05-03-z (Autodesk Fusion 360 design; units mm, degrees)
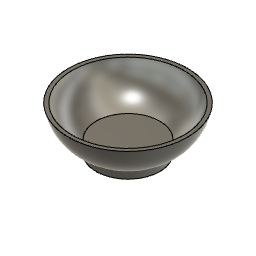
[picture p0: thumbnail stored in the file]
sketch "スケッチ1" plane through (0, 0, 0) normal (0, 0, 1) x axis (1, 0, 0)
  line L1 (-7, -2) -> (-8, -2)
  line L2 (-7, 0) -> (-7, -2)
  line L3 (-8, 0) -> (-7, 0)
  line L4 (-8, -2) -> (-8, 0)
  line L5 (0, 22.5) -> (0, 1.75)
  point P1 (0, 0)
  point P4 (-7, 0)
  point P2 (-8, -2)
  point P3 (-7, -2)
  point P5 (-8, 0)
  horizontal L1
  vertical L2
  horizontal L3
  vertical L4
  horizontal P1 P4
  dimension "d1" distance P2 P3 = 1
  dimension "d2" distance P2 P5 = 2
  dimension "d3" = 16
revolve "回転1" sketch "スケッチ1" AlongAngle 360
sketch "スケッチ2" plane through (0, 0, 0) normal (0, 0, 1) x axis (1, 0, 0)
  line L1 (-8, 0) -> (0, 0)
  line L2 (-8, 1) -> (-8, 0)
  line L3 (0, 1) -> (-8, 1)
  line L4 (0, 0) -> (0, 1)
  line L5 (-8, -2) -> (-8, 0)
  line L6 (8, 0) -> (8, -2)
  point P1 (0, 0)
  point P2 (0, 0)
  point P3 (-8, 0)
  point P4 (-8, 1)
  horizontal L1
  vertical L2
  horizontal L3
  vertical L4
  coincident P1 P2
  collinear L2 L5
  dimension "d5" distance P3 P4 = 1
revolve "回転2" sketch "スケッチ2" AlongAngle 360
sketch "スケッチ3" plane through (0, 0, 0) normal (0, 0, 1) x axis (1, 0, 0)
  line L1 (-14.0784, 9) -> (-15, 9)
  line L2 (-8, 0) -> (-8, 1)
  line L3 (-8, -2) -> (-8, 1)
  line L4 (8, 1) -> (8, -2)
  line L5 (0, 22.5) -> (0, 1.75)
  arc A1 centre (-3.1649, 10.9828) radius 11.0921 clockwise from (-8, 1) to (-14.0784, 9)
  arc A2 centre (-3.1649, 10.9828) radius 12 clockwise from (-8, 0) to (-15, 9)
  point P3 (-8, 1)
  point P8 (-8, 1)
  point P1 (0, 0)
  point P6 (-8, 0)
  vertical L2
  horizontal L1
  concentric A1 A2
  coincident P3 P8
  horizontal P1 P6
  dimension "d7" distance P1 L1 = 9
  dimension "d8" radius A2 = 12
  dimension "d9" = 30
revolve "回転3" sketch "スケッチ3" AlongAngle 360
